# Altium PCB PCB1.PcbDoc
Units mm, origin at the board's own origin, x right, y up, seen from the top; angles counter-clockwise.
Board outline 152.4 x 101.6 mm, 2 copper layers (Top Layer, Bottom Layer); 8 components, 10 nets, 29 pads, 0 vias.
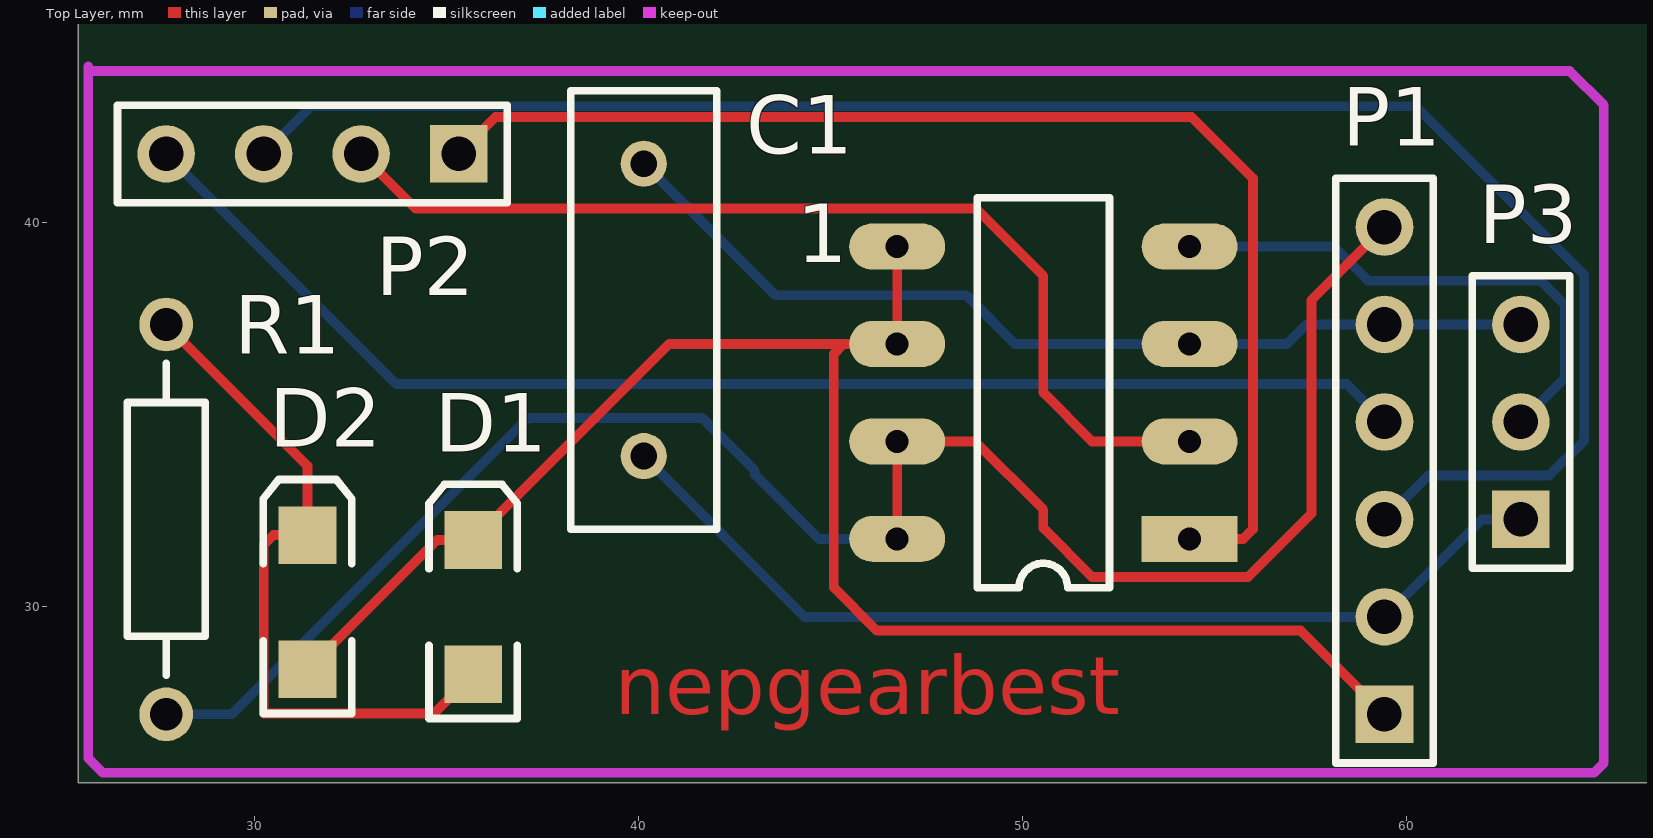
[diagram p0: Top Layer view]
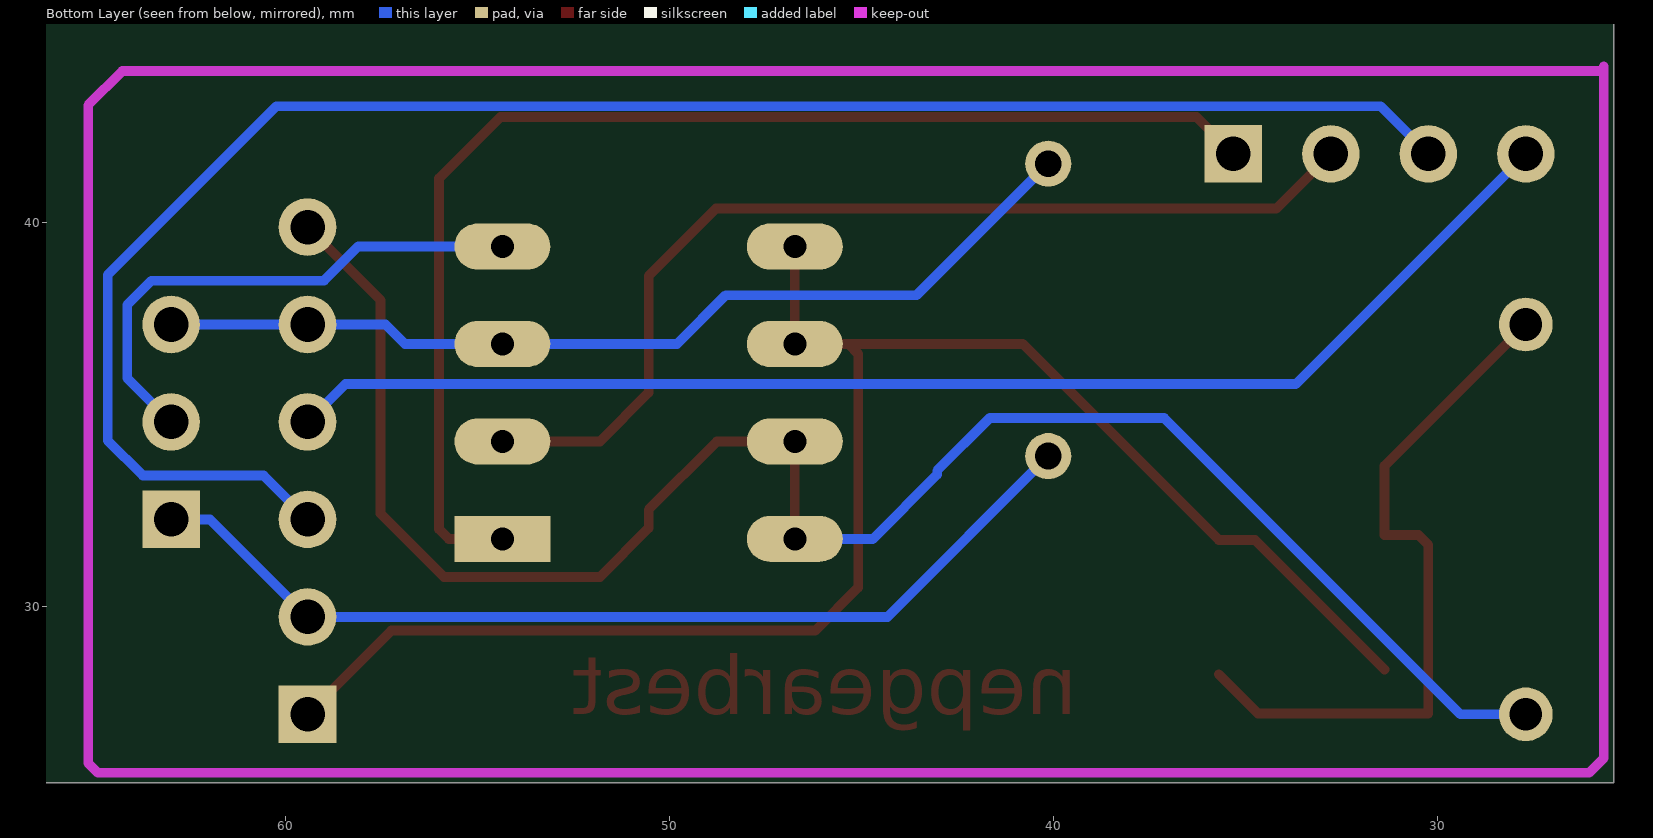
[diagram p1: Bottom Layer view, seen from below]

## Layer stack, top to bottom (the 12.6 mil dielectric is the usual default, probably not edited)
Top Solder: solder mask 0.0102, Solder Resist, Dk 3.5
Top Layer: signal copper 0.0356
Dielectric 1: dielectric 0.32, FR-4, Dk 4.8
Bottom Layer: signal copper 0.0356
Bottom Solder: solder mask 0.0102, Solder Resist, Dk 3.5

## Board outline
25.4,25.4 177.8,25.4 177.8,127 25.4,127

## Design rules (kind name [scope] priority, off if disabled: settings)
Clearance [All] p1: gap=0.254
PolygonConnect [All] p1: connectstyle=Relief reliefconductorwidth=0.254 reliefentries=4 polygonreliefangle="90 Angle" airgapwidth=0.254
RoomDefinition Sheet1 [InComponentClass('Sheet1')] p1: confinementstyle=ConfineIn formatcopy=TRUE lockcomponents=FALSE outline 25.654,25.499 65.151,25.499 65.151,44.069 25.654,44.069
RoutingVias [All] p1: holewidth=0.711 width=1.27 viastyle="Through Hole" minholewidth=0.711 minwidth=1.27 maxholewidth=0.711 maxwidth=1.27
SolderMaskExpansion [All] p1: expansion=0.102
UnpouredPolygon [All] p1: allowunpoured=FALSE
Width [All] p1: maxlimit=0.254 minlimit=0.254 preferedwidth=0.254
29 further rules are at their usual default settings.

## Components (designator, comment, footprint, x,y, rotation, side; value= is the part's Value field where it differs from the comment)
1 "RZ7886" "RZ7886 - duplicate" 54.356,31.75 r180 top
C1 "Cap" RAD-0.3 40.132,37.719 r90 top
D1 "LED2" 3.2X1.6X1.1 35.687,29.972 r90 top
D2 "LED2" 3.2X1.6X1.1 31.369,30.099 r90 top
P1 "Header 6" HDR1X6 59.436,27.178 r90 top
P2 "Header 4" HDR1X4 35.306,41.783 r180 top
P3 "Header 3" HDR1X3 62.992,32.258 r90 top
R1 "Res2" AXIAL-0.4 27.686,32.258 r90 top

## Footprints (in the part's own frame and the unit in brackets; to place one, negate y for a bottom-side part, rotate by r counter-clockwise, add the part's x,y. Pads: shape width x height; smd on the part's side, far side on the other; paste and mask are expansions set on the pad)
3.2X1.6X1.1 [mm] "SMT LED; 2 Flat Leads"
  rect 1.5x1.5 smd: 1(-1.75,0) 2(1.75,0)
  silkscreen extent -2.9,-1.15 3.2,1.15
AXIAL-0.4 [mm] "Axial Device, Thru-Hole; 2 Leads; 0.4 in Pin Spacing"
  round 1.4 hole 0.85: 1(-5.08,0) 2(5.08,0)
  silkscreen extent -4.06,-1.02 4.06,1.02
HDR1X3 [mm] "Connector; Header; 3 Position"
  rect 1.5x1.5 hole 0.9: 1(0,0)
  round 1.5 hole 0.9: 2(2.54,0) 3(5.08,0)
  silkscreen extent -1.27,-1.27 6.35,1.27
HDR1X4 [mm] "Connector; Header; 4 Position"
  rect 1.5x1.5 hole 0.9: 1(0,0)
  round 1.5 hole 0.9: 2(2.54,0) 3(5.08,0) 4(7.62,0)
  silkscreen extent -1.27,-1.27 8.89,1.27
HDR1X6 [mm] "Connector; Header; 6 Position"
  rect 1.5x1.5 hole 0.9: 1(0,0)
  round 1.5 hole 0.9: 2(2.54,0) 3(5.08,0) 4(7.62,0) 5(10.16,0) 6(12.7,0)
  silkscreen extent -1.27,-1.27 13.97,1.27
RAD-0.3 [mm] "Radial Cap, Thru-Hole; 2 Leads; 0.3 in Pin Spacing"
  round 1.2 hole 0.7: 1(-3.81,0) 2(3.81,0)
  silkscreen extent -5.71,-1.91 5.71,1.91
"RZ7886 - duplicate" [mm]
  rect 2.5x1.2 hole 0.6: 1(0,0)
  oval 2.5x1.2 hole 0.6: 2(0,-2.54) 3(0,-5.08) 4(0,-7.62) 5(7.62,-7.62) 6(7.62,-5.08) 7(7.62,-2.54) 8(7.62,0)
  silkscreen extent 2.08,-8.89 5.54,1.27

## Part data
C1: "Capacitor"
D1 D2: "Typical RED, GREEN, YELLOW, AMBER GaAs LED"
P1: "Header, 6-Pin"
P2: "Header, 4-Pin"
P3: "Header, 3-Pin"
R1: "Resistor"

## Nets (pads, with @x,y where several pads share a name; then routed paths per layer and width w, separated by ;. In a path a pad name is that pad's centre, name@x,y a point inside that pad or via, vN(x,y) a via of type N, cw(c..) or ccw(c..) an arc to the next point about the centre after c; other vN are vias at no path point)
5V: C1.1 P1.2 P3.1 | length 25.6
  Bottom Layer w0.254: C1.1 44.323,29.718 P1.2 61.976,32.258 P3.1
GND: 1.3 C1.2 P1.5 P3.3 | length 25
  Bottom Layer w0.254: C1.2 43.561,38.1 48.539,38.1 49.809,36.83 1.3 56.896,36.83 57.404,37.338 P1.5 P3.3
NetD1_1: D1.1 D2.2 R1.2 | length 18.5
  Top Layer w0.254: R1.2 31.369,33.655 D2.2 30.48,31.849 30.226,31.595 30.226,27.203 34.668,27.203 D1.1
O1: 1.5 1.6 D1.2 D2.1 P1.1 | length 43.6
  Top Layer w0.254: D2.1 34.742,31.722 D1.2 40.795,36.83 45.339,36.83 ; 1.5 1.6 45.339,36.83 ; P1.1 57.252,29.362 46.203,29.362 45.085,30.48 45.085,36.576 45.339,36.83
O2: 1.7 1.8 P1.6 R1.1 | length 47.6
  Top Layer w0.254: 1.8 1.7 48.768,34.29 50.546,32.512 50.546,32.029 51.816,30.759 55.88,30.759 57.531,32.41 57.531,37.973 P1.6
  Bottom Layer w0.254: R1.1 29.388,27.178 37.109,34.9 41.656,34.9 43.028,33.528 43.028,33.426 44.704,31.75 1.8
PA6: P1.4 P2.4 | length 34.6
  Bottom Layer w0.254: P2.4 33.68,35.789 58.445,35.789 P1.4
PA7: P1.3 P2.3 | length 47.1
  Bottom Layer w0.254: P2.3 31.471,43.028 60.249,43.028 64.643,38.633 64.643,34.315 63.729,33.401 60.579,33.401 P1.3
PB8: 1.1 P2.1 | length 32.7
  Top Layer w0.254: P2.1 36.271,42.748 54.407,42.748 56.007,41.148 56.007,32.004 55.753,31.75 1.1
PB9: 1.2 P2.2 | length 26.5
  Top Layer w0.254: P2.2 34.188,40.361 48.793,40.361 50.546,38.608 50.546,35.56 51.816,34.29 1.2
PWR: 1.4 P3.2 | length 13.9
  Bottom Layer w0.254: 1.4 58.115,39.37 59.004,38.481 63.5,38.481 64.135,37.846 64.135,35.941 P3.2

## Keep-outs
Keep-Out Layer:
  lines w0.254: 25.654,43.942 64.262,43.942 65.151,43.053 65.151,25.908 64.897,25.654 26.035,25.654 25.654,26.035 25.654,44.069

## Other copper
Top Layer:
  text "nepgearbest" at 39.37,27.178 h1.52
